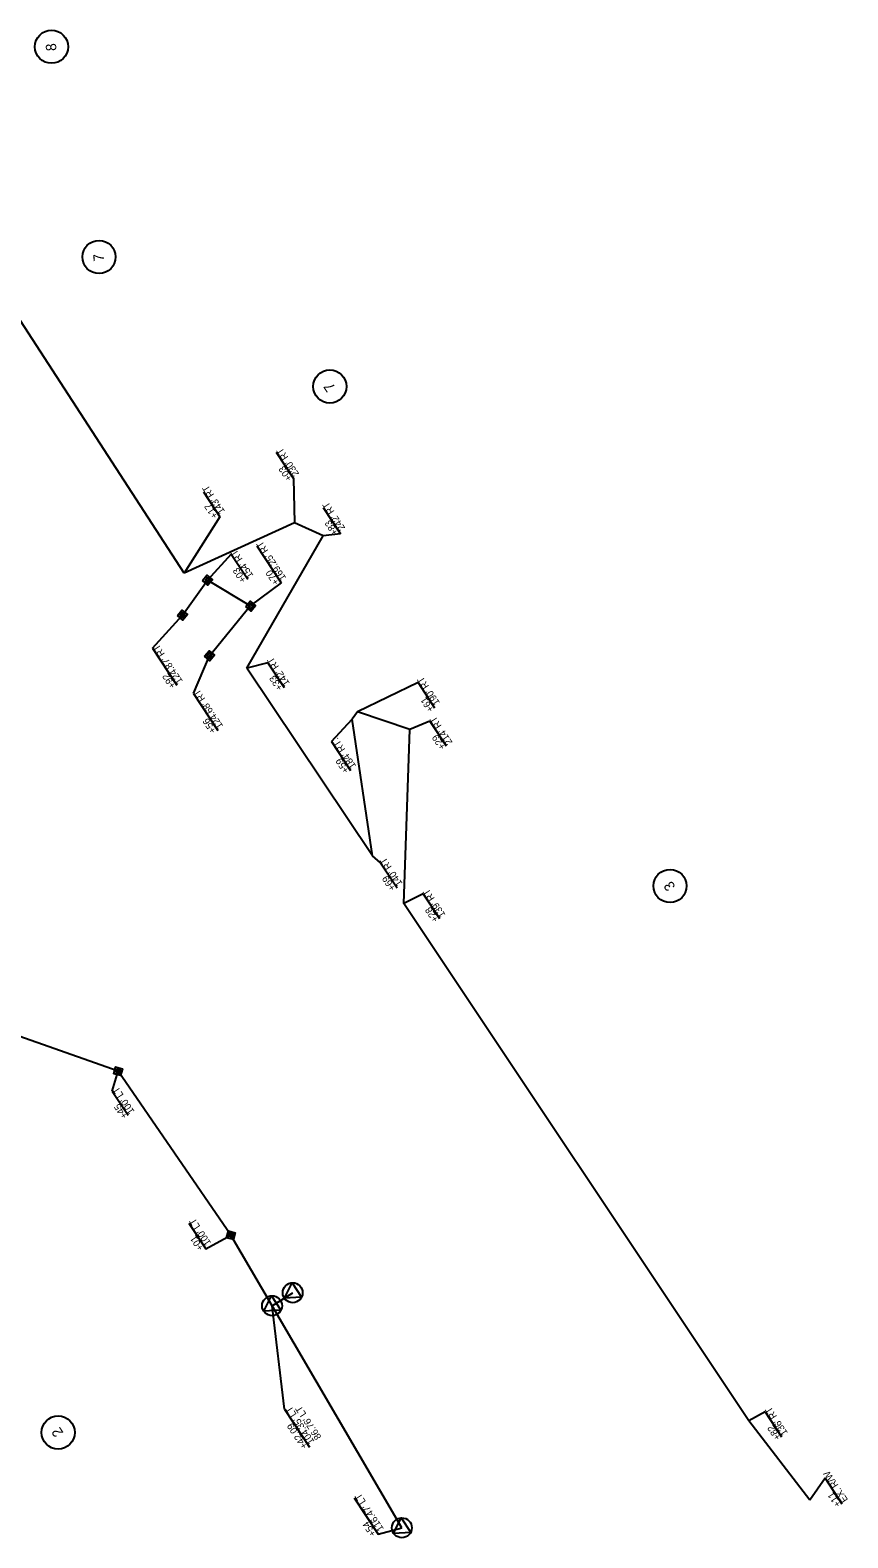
# Model space of a CAD drawing. Extents: x 1555582 to 1558054, y 687961 to 694065.
# Drawn here: x 1556553 to 1557145, y 689751 to 690842 of the extents above; entities that cross this region are included whole.
import ezdxf

# ---------------------------------------------------------------- set-up
doc = ezdxf.new("R2010")
doc.units = 0
for name, color, linetype in [('Exist Horizontal Alignment', 7, 'Continuous'), ('Exist Structure Major Bridge Seam', 7, 'Continuous'), ('Prop Approach Slab Hatching', 7, 'Continuous'), ('Prop Drainage Structure Catch Basin Grate 840 03F CELL', 7, 'Continuous'), ('Prop Drainage Structure Catch Basin Grate 840 03F Label', 7, 'Continuous'), ('Prop Drainage Structure Catch Basin Grate 840 03G CELL', 7, 'Continuous'), ('Prop Drainage Structure Plot Symbol 20 Scale', 7, 'Continuous'), ('Prop Drainage Structure Plot Symbol 50 Scale', 7, 'Continuous'), ('Prop Erosion Rip Rap Class II', 7, 'Continuous'), ('Prop Erosion Rip Rap Single Stone CELL', 7, 'Continuous'), ('Prop Plan Preparation Excavation Hatching', 7, 'Continuous'), ('Scratch_Level_3', 7, 'Continuous')]:
    doc.layers.add(name, color=color, linetype=linetype)

msp = doc.modelspace()

# ---------------------------------------------------------------- linework, layer by layer
at = {"layer": 'Exist Horizontal Alignment'}
for q in [(1556728.1, 689919.2), (1556755.1, 689816.8)]:
    msp.add_line((1556737, 689844.4), q, dxfattribs=at)
msp.add_lwpolyline([(1556787.5, 689780.1), (1556804.8, 689753.8), (1556822, 689758.5)], dxfattribs=at)
at = {"layer": 'Exist Structure Major Bridge Seam'}
for p, q in [((1556717, 690469.1), (1556734.6, 690442.3)), ((1556698.5, 690463), (1556710.5, 690444.8)), ((1556641.7, 690395), (1556663.2, 690418.9)), ((1556641.7, 690395), (1556659.3, 690368.3)), ((1556671.3, 690362.1), (1556682.8, 690389.5)), ((1556671.3, 690362.1), (1556688.9, 690335.3))]:
    msp.add_line(p, q, dxfattribs=at)
for points in [[(1556698.5, 690463), (1556681.4, 690444.1)], [(1556734.6, 690442.3), (1556712.2, 690425.5)]]:
    msp.add_lwpolyline(points, dxfattribs=at)
at = {"layer": 'Prop Approach Slab Hatching'}
for p, q in [((1556681.4, 690444.1), (1556681.4, 690444.1)), ((1556712.5, 690425.3), (1556712.5, 690425.3)), ((1556663.2, 690418.9), (1556663.2, 690418.9)), ((1556682.8, 690389.5), (1556682.8, 690389.5)), ((1556616.7, 690088.9), (1556616.7, 690088.9)), ((1556698.3, 689970.2), (1556698.3, 689970.2)), ((1556743, 689928.6), (1556743, 689928.6)), ((1556728.1, 689919.2), (1556728.1, 689919.2)), ((1556822, 689758.5), (1556822, 689758.5))]:
    msp.add_line(p, q, dxfattribs=at)
for points in [[(1556749.4, 689925.4), (1556737, 689924.7), (1556742.6, 689935.8)], [(1556734.5, 689915.9), (1556722.1, 689915.3), (1556727.7, 689926.4)], [(1556828.5, 689755.2), (1556816, 689754.5), (1556821.6, 689765.7)]]:
    msp.add_lwpolyline(points, close=True, dxfattribs=at)
for centre in [(1556743, 689928.6), (1556728.1, 689919.2), (1556822, 689758.5)]:
    msp.add_circle(centre, 7.2, dxfattribs=at)
at = {"layer": 'Prop Drainage Structure Catch Basin Grate 840 03F CELL'}
for p, q in [((1556731.1, 690536.8), (1556743.6, 690517.8)), ((1556678.4, 690508.1), (1556690.3, 690490.1)), ((1556765.1, 690496.8), (1556777.6, 690477.7)), ((1556725, 690384.4), (1556736.9, 690366.4)), ((1556833.7, 690370), (1556845.5, 690351.9)), ((1556842.2, 690342.2), (1556854, 690324.2)), ((1556771.1, 690327.5), (1556784.8, 690306.5)), ((1556806.6, 690239.6), (1556818.5, 690221.6)), ((1556837.4, 690217.3), (1556849.3, 690199.3)), ((1557084.9, 689842.4), (1557096.7, 689824.4)), ((1557128.1, 689794.4), (1557140.2, 689775.9))]:
    msp.add_line(p, q, dxfattribs=at)
for points in [[(1556743.6, 690517.8), (1556744.3, 690485.7)], [(1556690.3, 690490.1), (1556664.6, 690449.3)], [(1556777.6, 690477.7), (1556765.1, 690476.3)], [(1556725, 690384.4), (1556709.9, 690380.5)], [(1556833.7, 690370), (1556789.9, 690348.8)], [(1556771.1, 690327.5), (1556786.1, 690343.7)], [(1556842.2, 690342.2), (1556827.8, 690336)], [(1556806.6, 690239.6), (1556800.8, 690244.6)], [(1556837.4, 690217.3), (1556823.3, 690210.3)], [(1557084.9, 689842.4), (1557072.9, 689835.8)], [(1557128.1, 689794.4), (1557117.2, 689778.4)]]:
    msp.add_lwpolyline(points, dxfattribs=at)
at = {"layer": 'Prop Drainage Structure Catch Basin Grate 840 03F Label'}
for p, q in [((1556568.5, 690830.1), (1556568.5, 690830.1)), ((1556602.9, 690678), (1556602.9, 690678)), ((1556769.9, 690584.3), (1556769.9, 690584.3)), ((1557016, 690222.9), (1557016, 690222.9)), ((1556573.3, 689827.5), (1556573.3, 689827.5))]:
    msp.add_line(p, q, dxfattribs=at)
for centre in [(1556568.5, 690830.1), (1556602.9, 690678), (1556769.9, 690584.3), (1557016, 690222.9), (1556573.3, 689827.5)]:
    msp.add_circle(centre, 12, dxfattribs=at)
at = {"layer": 'Prop Drainage Structure Plot Symbol 20 Scale'}
for p, q in [((1556728.1, 689919.2), (1556743, 689928.6)), ((1556822, 689758.5), (1556728.1, 689919.2))]:
    msp.add_line(p, q, dxfattribs=at)
at = {"layer": 'Prop Drainage Structure Plot Symbol 50 Scale'}
msp.add_line((1556612.5, 690074.5), (1556624.1, 690057), dxfattribs=at)
for points in [[(1556612.5, 690074.5), (1556616.7, 690088.9)], [(1556667.9, 689979), (1556680.1, 689960.3), (1556698.3, 689970.2)]]:
    msp.add_lwpolyline(points, dxfattribs=at)
at = {"layer": 'Prop Erosion Rip Rap Class II'}
for p, q in [((1556663.2, 690418.9), (1556681.4, 690444.1)), ((1556712.2, 690425.5), (1556681.4, 690444.1)), ((1556682.8, 690389.5), (1556712.2, 690425.5))]:
    msp.add_line(p, q, dxfattribs=at)
at = {"layer": 'Prop Erosion Rip Rap Single Stone CELL'}
for p, q in [((1556664.6, 690449.3), (1556528.6, 690658.6)), ((1556744.3, 690485.7), (1556664.6, 690449.3)), ((1556765.1, 690476.3), (1556744.3, 690485.7)), ((1556709.9, 690380.5), (1556765.1, 690476.3)), ((1556800.8, 690244.6), (1556709.9, 690380.5)), ((1556789.9, 690348.8), (1556786.1, 690343.7)), ((1556827.8, 690336), (1556789.9, 690348.8)), ((1556800.8, 690244.6), (1556786.1, 690343.7)), ((1556823.3, 690210.3), (1556827.8, 690336)), ((1557072.9, 689835.8), (1556823.3, 690210.3)), ((1557117.2, 689778.4), (1557072.9, 689835.8))]:
    msp.add_line(p, q, dxfattribs=at)
at = {"layer": 'Prop Plan Preparation Excavation Hatching'}
for p, q in [((1556616.7, 690088.9), (1556494.3, 690132.1)), ((1556698.3, 689970.2), (1556616.7, 690088.9)), ((1556728.1, 689919.2), (1556698.3, 689970.2))]:
    msp.add_line(p, q, dxfattribs=at)
at = {"layer": 'Scratch_Level_3'}
for points in [[(1556677.8, 690443.8), (1556681, 690447.7), (1556684.9, 690444.4), (1556681.7, 690440.5)], [(1556679.6, 690443.9), (1556681.2, 690445.9), (1556683.2, 690444.3), (1556681.5, 690442.3)], [(1556659.6, 690418.6), (1556662.8, 690422.5), (1556666.8, 690419.2), (1556663.5, 690415.3)], [(1556709, 690425), (1556712.2, 690428.9), (1556716.1, 690425.7), (1556712.9, 690421.7)], [(1556710.8, 690425.2), (1556712.4, 690427.1), (1556714.3, 690425.5), (1556712.7, 690423.5)], [(1556661.4, 690418.7), (1556663, 690420.7), (1556665, 690419.1), (1556663.3, 690417.1)], [(1556679.2, 690389.1), (1556682.5, 690393), (1556686.4, 690389.8), (1556683.1, 690385.9)], [(1556681, 690389.3), (1556682.7, 690391.3), (1556684.6, 690389.6), (1556683, 690387.7)], [(1556613.6, 690087), (1556614.9, 690092), (1556619.8, 690090.7), (1556618.5, 690085.7)], [(1556615.1, 690087.9), (1556615.8, 690090.4), (1556618.3, 690089.8), (1556617.6, 690087.3)], [(1556695.2, 689968.4), (1556696.5, 689973.3), (1556701.4, 689972), (1556700.1, 689967.1)], [(1556696.7, 689969.3), (1556697.4, 689971.8), (1556699.9, 689971.1), (1556699.2, 689968.7)]]:
    msp.add_lwpolyline(points, close=True, dxfattribs=at)

# ---------------------------------------------------------------- texts
at = {"layer": 'Exist Horizontal Alignment'}
for s, rotation, p in [("104.35' LT", 123.2524, (1556759, 689820.9)), ("86.76' LT", 123.2524, (1556764, 689824.2)), ('+42.09', 123.2524, (1556754, 689817.6)), ("116.47' LT", 123.2617, (1556809.1, 689757.8)), ('+54', 123.2617, (1556803.6, 689754.2))]:
    msp.add_text(s, height=5, rotation=rotation, dxfattribs=at).set_placement(p)
at = {"layer": 'Exist Structure Major Bridge Seam'}
for s, p in [("169.25' RT", (1556738.5, 690445.8)), ("154' RT", (1556714.8, 690447.5)), ('+03', (1556709.7, 690444.3)), ('+70', (1556733.5, 690442.6)), ("124.87' RT", (1556663.7, 690371.1)), ('+92', (1556658.7, 690367.8)), ("124.68' RT", (1556692.9, 690338.6)), ('+56', (1556687.9, 690335.3))]:
    msp.add_text(s, height=5, rotation=123.2617, dxfattribs=at).set_placement(p)
at = {"layer": 'Prop Drainage Structure Catch Basin Grate 840 03F CELL'}
for s, p in [("230' RT", (1556747.9, 690521.1)), ('+03', (1556742.9, 690517.8)), ("143' RT", (1556694.2, 690494)), ('+17', (1556689.2, 690490.7)), ("242' RT", (1556781.2, 690481.9)), ('+83', (1556776.2, 690478.6)), ("142' RT", (1556741.1, 690369.6)), ('+33', (1556736.1, 690366.3)), ("190' RT", (1556849.7, 690355.5)), ('+61', (1556845.4, 690350.7)), ("214' RT", (1556858.8, 690326.8)), ("184' RT.", (1556789.1, 690309.7)), ('+29', (1556853.8, 690323.5)), ('+59', (1556784.1, 690306.5)), ("140' RT", (1556822.7, 690224.7)), ('+69', (1556817.7, 690221.4)), ("139' RT", (1556853.8, 690202)), ('+28', (1556848.8, 690198.7)), ("136' RT", (1557101.4, 689827.2)), ('+82', (1557096.4, 689823.9)), ('EX. R/W', (1557144.9, 689778.8)), ('+11', (1557139.9, 689775.5))]:
    msp.add_text(s, height=5, rotation=123.2617, dxfattribs=at).set_placement(p)
at = {"layer": 'Prop Drainage Structure Catch Basin Grate 840 03G CELL'}
for s, rotation, p in [('8', 95.1414, (1556572.2, 690827.3)), ('7', 95.1414, (1556606.6, 690675.1)), ('7', 123.2617, (1556774.3, 690583.5)), ('3', 123.2617, (1557020.2, 690222.4)), ('2', 123.2617, (1556577.4, 689827.3))]:
    msp.add_text(s, height=7.5, rotation=rotation, dxfattribs=at).set_placement(p)
at = {"layer": 'Prop Drainage Structure Plot Symbol 50 Scale'}
for s, rotation, p in [("100' LT", 123.544, (1556628.8, 690059.8)), ('+45', 123.544, (1556623.8, 690056.5)), ("100' LT", 123.2617, (1556684.2, 689964.6)), ('+01', 123.2617, (1556678.8, 689961))]:
    msp.add_text(s, height=5, rotation=rotation, dxfattribs=at).set_placement(p)

doc.saveas('drawing.dxf')
